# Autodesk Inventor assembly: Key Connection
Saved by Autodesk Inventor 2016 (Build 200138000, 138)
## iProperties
Created: 2015-08
Part Number: Key Connection
Document SubType Name: Assembly
Designer: Ugljesa
ClientObjectVersion: 1
Author: Ugljesa
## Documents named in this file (1)
- C:\Users\Ugljesa\Desktop\Turbokompr\Sklop turbokompresora\Design Accelerator\Key Connection2.iam
